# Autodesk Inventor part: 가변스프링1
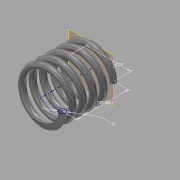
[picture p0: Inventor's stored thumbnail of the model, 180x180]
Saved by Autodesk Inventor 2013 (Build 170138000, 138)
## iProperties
Created: 2015-02
Part Number: 가변스프링1
Material: 강철, 탄소
Document SubType Name: Modeling
Designer: Administrator
Density: 7.87 g/cm^3
Mass: 18.7439 g
Surface Area: 32.3998 cm^2
Volume: 2.3817 cm^3
Author: Administrator
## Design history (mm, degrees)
sketch "스케치1"
  geometry: L1 (0, 0)-(11, 0); L2 (11, 0)-(11, 25.358); L3 (11, 25.358)-(0, 25.358); L4 (0, 25.358)-(0, 0); C1 r 1.5 at (11, 0)
  constraints: 8 end point, 2 parallel, 1 centre point, 1 coincident, 1 horizontal, 1 perpendicular
  dimensions: "d0" = 22 diameter of L2 L4; "d2" = 25.35829 distance of L1.end L2.end (derived); "d3" = 3 diameter of C1
feature "코일1" pitch "d4" = 10; turns "d6" = 5; dims "d5" = 25.35829 (= d2), "d7" = 0, angle "d8" = 90 deg, angle "d9" = 90 deg, "d10" = 0, "d11" = 0
sketch "스케치2"
  geometry: L1 (-12.5, 0)-(-9.5, 0) reference; 1 further point
  constraints: 1 horizontal alignment
extrude "돌출1" cut sketch "스케치2" stored distance "d12" = 10; taper "d13" = 0 deg
node "작업 평면1"
sketch "스케치3"
  geometry: L1 (12.5, 0)-(9.5, 0) reference; 1 further point
  constraints: 1 horizontal alignment
extrude "돌출2" cut sketch "스케치3" stored distance "d14" = 10; taper "d15" = 0 deg
node "솔리드1"
node "절단 모서리 투영1"
node "절단 모서리 투영2"
